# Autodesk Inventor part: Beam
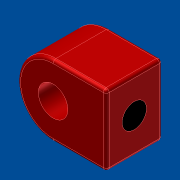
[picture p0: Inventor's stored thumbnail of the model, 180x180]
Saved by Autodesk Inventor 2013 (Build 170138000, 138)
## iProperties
Shininess: 20.0
Length Units: 11269
Angle Units: 11279
Time Units: 11290
Mass Units: 11283
Length Display Precision: 3
Angle Display Precision: 2
Created: 2001-04
Part Number: Beam
Material: Standard
Document SubType Name: Modellieren
Designer: dl
Density: 1 g/cm^3
Density: 0.0
Volumn: 0.0
Area: 0.0
PropertySet Name: Model Information
Control State: 0
Master: False
Checked Out: False
Author: dl
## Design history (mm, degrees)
sketch "Sketch3"
  geometry: L1 (0, 12)-(0, 0) reference; L2 (0, 12)-(-9.5, 12) reference; 1 further point
  dimensions: "d11" = 4.75 distance from line of L1 point (-4.75, 6); "d12" = 6 distance from line of point (-4.75, 6) L2
body "Solid1"
sketch "Sketch1"
  geometry: L1 (17.218, 5.727)-(26.218, 5.727); L2 (26.218, 5.727)-(26.218, -6.273); L3 (26.218, -6.273)-(17.218, -6.273); A1 r 6 centre (17.218, -0.273) between (17.218, 5.727) and (17.218, -6.273)
  constraints: 6 end point, 2 point on circle, 2 tangent, 1 centre point, 1 horizontal, 1 parallel, 1 perpendicular
  dimensions: "d0" = 12 distance of L1.end L2.end; "d1" = 9 distance of L1.start L1.end
extrude "Extrusion1" new body sketch "Sketch1" distance "d2" = 9.5; taper "d3" = 0 deg
sketch "Sketch2"
  geometry: A1 r 6 centre (17.218, -0.273) between (17.218, 5.727) and (17.218, -6.273) reference; 1 further point
  constraints: 1 coincident
hole "Hole1" sketch "Sketch2" diameter "d4" = 5; stored, may be unused: countersink angle "d8" = 60 deg, drill point angle "d10" = 118 deg; dims "d5" = 6, "d6" = 4, "d7" = 2, "d9" = 8
hole "Hole2" sketch "Sketch3" diameter "d13" = 4.134; stored, may be unused: countersink angle "d17" = 60 deg, drill point angle "d19" = 0 deg; dims "d14" = 5, "d15" = 4, "d16" = 2, "d18" = 6
fillet "Fillet1" dims "d20" = 0.5
